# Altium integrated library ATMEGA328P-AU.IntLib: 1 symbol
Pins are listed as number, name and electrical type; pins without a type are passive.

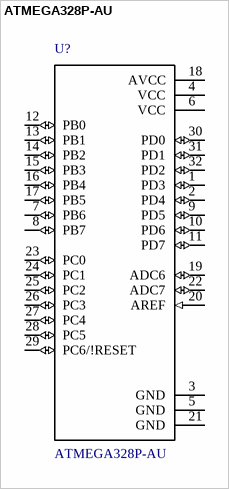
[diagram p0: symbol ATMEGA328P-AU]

## ATMEGA328P-AU
designator U?
AVR AVRÂ® ATmega Microcontroller IC 8-Bit 20MHz 32KB (16K x 16) FLASH 32-TQFP (7x7); MF: Microchip Technology
footprint *QFP80P900X900X120-32N
pins: 1 PD3 (io), 2 PD4 (io), 3 GND (power), 4 VCC (power), 5 GND (power), 6 VCC (power), 7 PB6 (io), 8 PB7 (io), 9 PD5 (io), 10 PD6 (io), 11 PD7 (io), 12 PB0 (io), 13 PB1 (io), 14 PB2 (io), 15 PB3 (io), 16 PB4 (io), 17 PB5 (io), 18 AVCC (power), 19 ADC6 (io), 20 AREF (in), 21 GND (power), 22 ADC7 (io), 23 PC0 (io), 24 PC1 (io), 25 PC2 (io), 26 PC3 (io), 27 PC4 (io), 28 PC5 (io), 29 PC6/!RESET (io), 30 PD0 (io), 31 PD1 (io), 32 PD2 (io)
